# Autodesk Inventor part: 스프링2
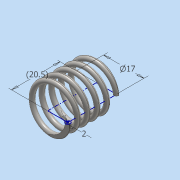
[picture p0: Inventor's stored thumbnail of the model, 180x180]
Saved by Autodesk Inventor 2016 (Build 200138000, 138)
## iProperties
Created: 2019-11
Part Number: 스프링2
Material: 스테인레스 스틸
Document SubType Name: Modeling
Designer: user
Density: 8 g/cm^3
Appearance: 반연마
Mass: 6.57605 g
Surface Area: 16.7268 cm^2
Volume: 0.822006 cm^3
Author: user
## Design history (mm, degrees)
sketch "스케치1"
  geometry: L1 (0, 0)-(8.5, 0); L2 (8.5, 0)-(8.5, 20.5); L3 (8.5, 20.5)-(0, 20.5); L4 (0, 20.5)-(0, 0); C1 r 1 at (8.5, 0)
  constraints: 8 end point, 2 parallel, 1 centre point, 1 coincident, 1 horizontal, 1 perpendicular
  dimensions: "d1" = 17 diameter of L2 L4; "d2" = 2 diameter of C1; "d3" = 20.5 distance of L3.end L1.start (derived)
feature "코일1" sketch "스케치1" pitch "d4" = 10; turns "d6" = 5; dims "d5" = 20.5 (= d3), "d7" = 0, angle "d8" = 90 deg, angle "d9" = 90 deg, "d10" = 0, "d11" = 0
sketch "스케치2"
  geometry: L1 (-15, 20.5)-(15, 20.5); L2 (15, 20.5)-(15, 0); L3 (15, 0)-(-15, 0); L4 (-15, 0)-(-15, 20.5); 2 further points
  constraints: 8 end point, 2 parallel, 1 coincident, 1 horizontal, 1 midpoint, 1 perpendicular
  dimensions: "d12" = 20.5 distance of L3.end L1.start (= d3); "d13" = 30 distance of L1.start L1.end
extrude "돌출1" sketch "스케치2" stored distance "d14" = 117.5; taper "d15" = 0 deg
node "솔리드1"
